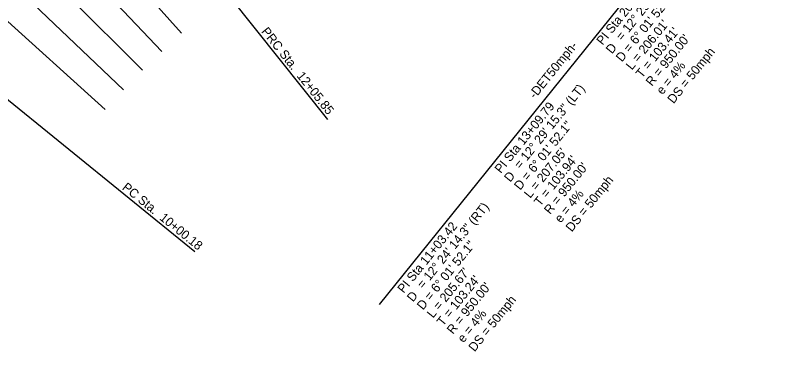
# Model space of a CAD drawing. Extents: x 2293233 to 2294507, y 892788 to 894229.
# Drawn here: x 2293545 to 2294145, y 892788 to 893049 of the extents above; entities that cross this region are included whole.
import ezdxf

# ---------------------------------------------------------------- set-up
doc = ezdxf.new("R2010")
doc.units = 0
for name, color, linetype in [('COGO Default Curve', 7, 'Continuous'), ('Prop Horizontal Alignment', 7, 'Continuous'), ('Prop Horizontal Alignment Station Label', 7, 'Continuous'), ('Scratch_Level_4', 7, 'Continuous')]:
    doc.layers.add(name, color=color, linetype=linetype)

msp = doc.modelspace()

# ---------------------------------------------------------------- linework, layer by layer
at = {"layer": 'COGO Default Curve'}
for radius in [956, 944]:
    msp.add_arc((2294209.34, 892440.82), radius, 128.6085, 141.01247, dxfattribs=at)
at = {"layer": 'Prop Horizontal Alignment'}
for p, q in [((2293828.53, 892824.42), (2294145.15, 893216.47)), ((2293617.48, 893182.01), (2293788.14, 892968.29)), ((2293472.08, 893037.57), (2293684.67, 892865.5))]:
    msp.add_line(p, q, dxfattribs=at)
msp.add_arc((2294209.34, 892440.82), 950, 128.6085, 141.01247, dxfattribs=at)
msp.add_arc((2294209.34, 892440.82), 950, 128.6085, 141.01247, dxfattribs=at)
at = {"layer": 'Scratch_Level_4'}
for p, q in [((2293473.62, 893258.58), (2293674.27, 893035.55)), ((2293452.36, 893238.94), (2293658.81, 893021.27)), ((2293431.62, 893218.74), (2293643.73, 893006.58)), ((2293411.42, 893198.01), (2293629.04, 892991.5)), ((2293391.78, 893176.75), (2293614.75, 892976.04))]:
    msp.add_line(p, q, dxfattribs=at)

# ---------------------------------------------------------------- texts
at = {"layer": 'Prop Horizontal Alignment'}
for s, rotation, p in [('= 12%%d 25\' 29.6" (LT)', 51.07477, (2294017.66, 893029.08)), ('PI Sta 20+05.37', 51.07477, (2294002.46, 893025.71)), ('D = 6%%d 01\' 52.1"', 51.07477, (2294017.6, 893012.62)), ("L = 206.01'", 51.07477, (2294025.37, 893006.33)), ('PRC Sta.  12+05.85', 308.6085, (2293736.09, 893036.67)), ("T = 103.41'", 51.07477, (2294033.15, 893000.05)), ("R = 950.00'", 51.07477, (2294040.93, 892993.77)), ('D', 51.07477, (2294009.82, 893018.9)), ('DS = 50mph', 51.07477, (2294057.81, 892980.14)), ('e = 4%', 51.07477, (2294049.17, 892987.12)), ('= 12%%d 29\' 15.3" (LT)', 51.07477, (2293938.34, 892929.28)), ('PI Sta 13+09.79', 51.07477, (2293923.14, 892925.9)), ('D = 6%%d 01\' 52.1"', 51.07477, (2293938.27, 892912.81)), ("L = 207.05'", 51.07477, (2293946.05, 892906.53)), ("T = 103.94'", 51.07477, (2293953.83, 892900.25)), ("R = 950.00'", 51.07477, (2293961.61, 892893.96)), ('D', 51.07477, (2293930.49, 892919.09)), ('PC Sta.  10+00.18', 321.01247, (2293627.46, 892914.38)), ('DS = 50mph', 51.07477, (2293978.48, 892880.34)), ('e = 4%', 51.07477, (2293969.84, 892887.31)), ('= 12%%d 24\' 14.3" (RT)', 51.07477, (2293862.58, 892836)), ('PI Sta 11+03.42', 51.07477, (2293847.38, 892832.63)), ('D = 6%%d 01\' 52.1"', 51.07477, (2293862.51, 892819.54)), ("L = 205.67'", 51.07477, (2293870.29, 892813.25)), ("T = 103.24'", 51.07477, (2293878.07, 892806.97)), ("R = 950.00'", 51.07477, (2293885.85, 892800.69)), ('D', 51.07477, (2293854.73, 892825.82)), ('DS = 50mph', 51.07477, (2293902.72, 892787.06)), ('e = 4%', 51.07477, (2293894.08, 892794.04))]:
    msp.add_text(s, height=7, rotation=rotation, dxfattribs=at).set_placement(p)
at = {"layer": 'Prop Horizontal Alignment Station Label'}
msp.add_text('-DET50mph-', height=7, rotation=51.09608, dxfattribs=at).set_placement((2293949.75, 892983.92))

doc.saveas('drawing.dxf')
